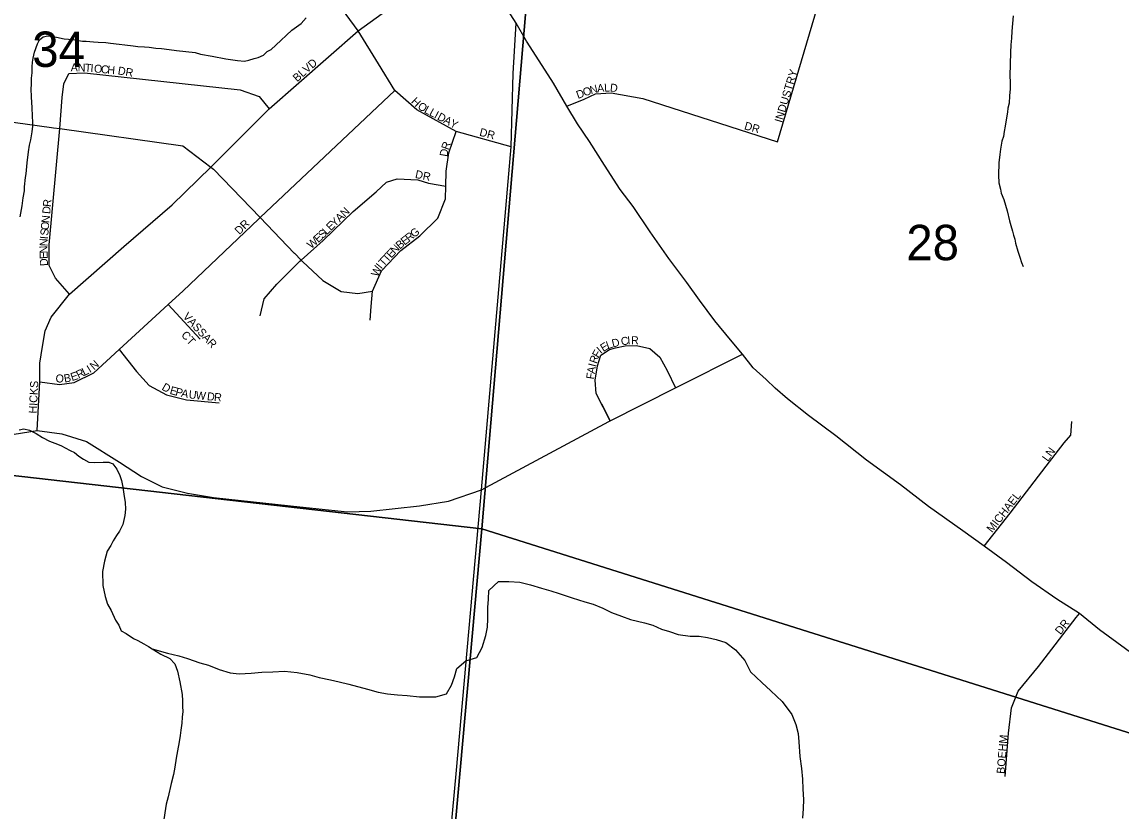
# Model space of a CAD drawing. Extents: x 1310247 to 1552180, y 377264 to 706493.
# Drawn here: x 1388764 to 1395630, y 491504 to 496435 of the extents above; entities that cross this region are included whole.
import ezdxf

# ---------------------------------------------------------------- set-up
doc = ezdxf.new("R2010")
doc.units = 0
for name, color, linetype in [('GM_X_City_Street', 7, 'Continuous'), ('GM_X_City_Street_Text', 7, 'Continuous'), ('GM_X_Minor_River', 7, 'Continuous'), ('GM_X_Section', 7, 'Continuous'), ('GM_X_Section_Text', 7, 'Continuous'), ('GM_X_State_Route', 7, 'Continuous')]:
    doc.layers.add(name, color=color, linetype=linetype)

msp = doc.modelspace()

# ---------------------------------------------------------------- linework, layer by layer
at = {"layer": 'GM_X_City_Street'}
for points in [[(1388858.2, 493882), (1388874.8, 494185.3), (1388875, 494301.6), (1388891.1, 494407.6), (1388908.9, 494503.6), (1388946.5, 494589.1), (1389061.3, 494733.4), (1389401.1, 495032), (1389702.7, 495292.1), (1389943.2, 495528.3), (1390307.7, 495891.8), (1390864.8, 496378.4), (1391178.7, 496608.5), (1391573.3, 496882.9), (1392264.6, 497329.3), (1392881.4, 497727.5), (1392929.2, 497820.9), (1392957.6, 498299.8)], [(1393484.5, 495686.5), (1393767, 496644.1), (1394171.8, 497915.6)], [(1391818.9, 495654.5), (1391475.3, 495749.8), (1391229.8, 495884.7), (1391093.9, 496007.1), (1390990.7, 496173.9), (1390864.8, 496378.4), (1390736.3, 496553.2), (1390644.8, 496707.3), (1390586.1, 496815.5), (1390559.3, 496872.4), (1390515, 496989.3), (1390484.1, 497166.6), (1390534, 497512.4), (1390552.9, 497662.5)], [(1391634.7, 493510.5), (1391818.9, 495654.5), (1391832.6, 496112.1), (1391851.9, 496427.8)], [(1389061.3, 494733.4), (1388973.1, 494833.3), (1388934.7, 494912.3), (1388933.2, 495042.4), (1388999.9, 495768.1), (1389014.6, 495963.4), (1389026.2, 496049.1), (1389057.5, 496113.5)], [(1389057.5, 496113.5), (1389153.6, 496117.7), (1390127.9, 496011.4), (1390245.1, 495969.2), (1390307.7, 495891.8)], [(1386085.1, 496049.9), (1386459, 496016.4), (1386828.5, 495981.4), (1387198.6, 495960.6), (1387320.9, 495952), (1388558.4, 495828.9), (1388571.9, 495827.6), (1388948.3, 495775.2), (1388960.6, 495773.5)], [(1388874.8, 494185.3), (1388998.5, 494169), (1389090.8, 494181.3), (1389212, 494241.2), (1389370.7, 494387.2), (1389677.2, 494669.2), (1389769.9, 494754.4), (1390240.6, 495203), (1390250.9, 495212.8), (1391093.9, 496007.1)], [(1392166.7, 495908), (1392275.4, 495951.6), (1392346.1, 495985.8), (1392444, 495992.2), (1392642.6, 495956.5), (1393484.5, 495686.5)], [(1388960.6, 495773.5), (1388999.9, 495768.1), (1389769.1, 495661), (1389943.2, 495528.3), (1389960.4, 495515.1), (1390250.9, 495212.8), (1390464.4, 494990.4), (1390465.7, 494989.2)], [(1390938.8, 494570.3), (1390944.4, 494656.5), (1390954.2, 494752.6), (1391010.6, 494879.9), (1391131.1, 495006.1), (1391248.9, 495098.1), (1391361, 495208.4), (1391409.3, 495329.8), (1391411.7, 495407.9), (1391414.6, 495502.3), (1391430.8, 495616.3), (1391475.3, 495749.8)], [(1390251.1, 494599.1), (1390277.1, 494704.9), (1390356.9, 494795.7), (1390499.6, 494939.5), (1390507.1, 494946.1), (1390646.1, 495069.2), (1390833.6, 495250.2), (1390976, 495374), (1391041.1, 495432.9), (1391107.6, 495453.8), (1391237.5, 495447.3), (1391303.2, 495428.1), (1391411.7, 495407.9)], [(1390465.7, 494989.2), (1390507.1, 494946.1), (1390515.6, 494937.2), (1390643.3, 494818.5), (1390758.1, 494750.2), (1390861.9, 494738.2), (1390954.2, 494752.6)], [(1389677.2, 494669.2), (1389876.2, 494451.6)], [(1392384.8, 494048.5), (1392438.3, 493942.4), (1392351.1, 494113.2), (1392345.2, 494195.7), (1392358.7, 494285.3), (1392379.6, 494351.8), (1392434.9, 494387.7), (1392472.5, 494397.8), (1392532.8, 494410.7), (1392602.9, 494413.4), (1392686, 494394.4), (1392748, 494339.9), (1392793.8, 494257.3), (1392846.2, 494148)], [(1388714.3, 493859.2), (1388858.2, 493882), (1389012.3, 493861.7), (1389167.7, 493813.7), (1389372.3, 493684.9), (1389511.2, 493594), (1389640, 493530.7), (1389798.3, 493489.2), (1389959.4, 493463.4), (1390442.1, 493410.8), (1390798.3, 493374.2), (1390942.3, 493378.5), (1391248, 493410.8), (1391428.6, 493439.9), (1391634.7, 493510.5), (1392430.8, 493938.6), (1392438.3, 493942.4), (1392846.2, 494148), (1392857.9, 494153.8), (1393264.8, 494359.7)], [(1389370.7, 494387.2), (1389480.2, 494250.3), (1389558.6, 494162.6), (1389667.5, 494104.4), (1389791, 494074.1), (1389994.7, 494054.3)], [(1394775.5, 493159.5), (1394937.4, 493366), (1395161.6, 493658.6), (1395274.5, 493805.7), (1395316.4, 493853.4), (1395322, 493937.6)], [(1391095.9, 487543.5), (1391100.6, 487596.7), (1391207.9, 488825.5), (1391477.6, 491759.9), (1391634.7, 493510.5)], [(1394905.7, 491718.9), (1394926.9, 491991.3), (1394945.9, 492149.4), (1394987.9, 492252.9), (1395114.8, 492407), (1395349.4, 492713.1), (1395369.6, 492737.7)]]:
    msp.add_lwpolyline(points, dxfattribs=at)
at = {"layer": 'GM_X_Minor_River'}
for points in [[(1389846.5, 496242.9), (1389878.4, 496234), (1389952.4, 496220.1), (1390038.3, 496203.8), (1390110.4, 496193.9), (1390154.5, 496190.8), (1390180.7, 496196.1), (1390215.2, 496207.3), (1390239.4, 496212.7), (1390272, 496228), (1390296.6, 496249.4), (1390321.1, 496262.8), (1390380.8, 496319.5), (1390415.9, 496352.8), (1390448.8, 496384.1), (1390508.2, 496424.8), (1390539.2, 496460.1)], [(1394956.6, 496472.9), (1394951.3, 496424.8), (1394948, 496376.7), (1394944.9, 496332.6), (1394941.8, 496292.5), (1394938.5, 496244.3), (1394934.6, 496097.8), (1394937.6, 496057.6), (1394936.5, 496017.4), (1394933.4, 495973.3), (1394930.1, 495927.2), (1394923.3, 495895.2), (1394920.6, 495871.2), (1394913.6, 495835.2), (1394906.2, 495783.2), (1394899.4, 495751.2), (1394894.5, 495719.2), (1394885.7, 495689.3), (1394881, 495665.3), (1394876.3, 495639.3), (1394871.5, 495607.3), (1394866.1, 495555.2), (1394864, 495476.9), (1394866.7, 495428.6), (1394875.8, 495390.2), (1394881.1, 495364), (1394898.2, 495325.4), (1394918.4, 495254.5), (1394932.8, 495191.9)], [(1388752.8, 495216.4), (1388764.7, 495286.4), (1388772, 495336.5), (1388779.2, 495380.5), (1388779.9, 495404.5), (1388785.4, 495462.7), (1388790.1, 495486.6), (1388795.9, 495554.8), (1388803.7, 495622.9), (1388810.9, 495664.9), (1388819.8, 495698.8), (1388827.1, 495748.8), (1388832, 495782.9), (1388832.7, 495807), (1388829.7, 495847.2), (1388827, 495897.5), (1388822.8, 495965.9), (1388822.1, 496016.1), (1388822.9, 496044.3), (1388823.9, 496084.4), (1388826.8, 496116.5), (1388827.8, 496154.6), (1388830.6, 496182.7), (1388833.2, 496208.7), (1388842.3, 496246.6), (1388861.7, 496298.4), (1388872.4, 496322.2), (1388897, 496341.7), (1388925.3, 496349), (1388949.4, 496346.3), (1388979.3, 496339.5), (1389027.3, 496330.3), (1389081.4, 496324.9), (1389141.4, 496315.3), (1389165.5, 496314.7), (1389211.6, 496311.5), (1389239.6, 496308.7), (1389287.8, 496305.5), (1389317.8, 496302.7), (1389371.9, 496295.3), (1389405.9, 496292.4), (1389458, 496285), (1389488, 496282.3), (1389530.1, 496279.2), (1389558.2, 496276.4), (1389600.2, 496271.3), (1389636.3, 496268.4), (1389682.4, 496263.2), (1389728.4, 496256), (1389786.5, 496250.5), (1389846.5, 496242.9)], [(1394932.8, 495191.9), (1394942.1, 495163.5), (1394951.2, 495127.1), (1394958.6, 495102.8), (1394965.9, 495076.5), (1394971.3, 495052.3), (1394984, 495001.8), (1394997.1, 494965.3), (1395008.2, 494930.8), (1395017.6, 494906.5)], [(1388745.8, 493886.8), (1388776.1, 493892), (1388810, 493883.1), (1388851.7, 493863.9), (1388891.2, 493838.8), (1388934.8, 493815.6), (1388986.5, 493796.2), (1389010.3, 493785.5), (1389034.1, 493772.9), (1389065.8, 493756), (1389091.5, 493743.3), (1389119.1, 493720.5), (1389148.7, 493703.6), (1389182.4, 493684.7), (1389218.5, 493681.8), (1389270.8, 493684.4), (1389306.9, 493683.5), (1389330.7, 493672.8), (1389356, 493640), (1389375, 493601.4), (1389386.2, 493569), (1389393.2, 493528.6), (1389400.1, 493484.2), (1389408.7, 493431.8), (1389409.6, 493389.6), (1389406.6, 493351.5), (1389393, 493293.6), (1389373.8, 493251.9), (1389355.1, 493226.2), (1389334.1, 493192.6), (1389319.3, 493162.9), (1389296.2, 493127.3), (1389278.5, 493065.5), (1389266.8, 493001.5), (1389268.5, 492913.1), (1389282.7, 492844.4), (1389297.5, 492795.8), (1389320.6, 492757.1), (1389347.1, 492696.1), (1389368.4, 492665.4), (1389383.6, 492630.9), (1389415.3, 492614), (1389460.6, 492582.7), (1389488.4, 492569.9), (1389526, 492548.9), (1389553.7, 492532.1), (1389577.4, 492517.4)], [(1389577.4, 492517.4), (1389673.5, 492491.3), (1389743.2, 492473.4), (1389797, 492457.9), (1389874.5, 492429.7), (1389928.3, 492416.1), (1389995.8, 492388.2), (1390065.4, 492368.2), (1390121.4, 492360.7), (1390195.8, 492364.7), (1390262.2, 492371), (1390330.5, 492373.1), (1390404.8, 492377.2), (1390482.9, 492369), (1390562.8, 492354.8), (1390620.5, 492339.2), (1390690.3, 492323.2), (1390746.2, 492311.7), (1390806, 492296), (1390921.5, 492264.8), (1390989.2, 492246.8), (1391047.2, 492237.2), (1391109.2, 492229.5), (1391169.3, 492225.9), (1391247.3, 492217.8), (1391299.4, 492216.4), (1391349.6, 492217), (1391416.4, 492235.3), (1391448, 492290.7), (1391465.5, 492342.5), (1391480.9, 492394.3), (1391536.4, 492443.1), (1391605.2, 492463.3), (1391639, 492524.7), (1391661.2, 492600.5), (1391672.6, 492652.4), (1391674.1, 492704.6), (1391674, 492775), (1391677.4, 492827.1), (1391680.9, 492881.3), (1391740.7, 492937.9), (1391804.9, 492938.2), (1391873, 492934.4), (1391940.8, 492916.5), (1392008.5, 492896.5), (1392068.2, 492880.8), (1392119.9, 492863.4), (1392201.5, 492837.1), (1392279, 492810.9), (1392332.8, 492797.3), (1392392.3, 492771.6), (1392445.7, 492744.1), (1392509.4, 492722.2), (1392565, 492700.7), (1392652.7, 492680.2), (1392704.4, 492664.7), (1392758, 492641.2), (1392809.7, 492625.7), (1392863.4, 492606.2), (1392937.4, 492596.2), (1392993.5, 492596.7), (1393045.5, 492589.2), (1393101.3, 492575.7), (1393161, 492556), (1393222, 492512.1), (1393280.3, 492444.2), (1393314.5, 492373), (1393384.9, 492306.8), (1393441.7, 492255), (1393512.1, 492188.8), (1393572.1, 492106.8), (1393598.4, 492043.8), (1393613, 491989.2), (1393617.6, 491936.8), (1393623.1, 491844.2), (1393633.1, 491769.6), (1393639.3, 491703.1), (1393641.6, 491640.8), (1393645.8, 491576.3), (1393644.3, 491520.1), (1393640.6, 491459.9)], [(1389577.4, 492517.4), (1389630.8, 492483.9), (1389688.3, 492456.3), (1389719.6, 492423.4), (1389734.5, 492378.8), (1389750.8, 492312.1), (1389764.7, 492231.4), (1389767.7, 492193.1), (1389766.8, 492157), (1389768, 492126.8), (1389765, 492090.7), (1389762, 492052.6), (1389756.8, 492008.6), (1389752, 491976.6), (1389744.9, 491936.6), (1389735.4, 491880.6), (1389728.1, 491834.5), (1389718.6, 491778.5), (1389711.4, 491732.5), (1389695.9, 491676.7), (1389677.6, 491592.8), (1389664.3, 491546.9), (1389659.6, 491518.9), (1389649.7, 491450.9)]]:
    msp.add_lwpolyline(points, dxfattribs=at)
at = {"layer": 'GM_X_Section'}
for points in [[(1386361.6, 499322.8), (1392089.7, 498619.6), (1391637.2, 493267.7), (1385887.9, 493921.2)], [(1392089.7, 498619.6), (1397269.5, 496943), (1396822, 491632.9), (1391637.2, 493267.7)], [(1385887.9, 493921.2), (1391637.2, 493267.7), (1391127.6, 487605), (1385461, 488464.6)], [(1391637.2, 493267.7), (1396822, 491632.9), (1396381.7, 486376.7), (1391127.6, 487605)]]:
    msp.add_lwpolyline(points, close=True, dxfattribs=at)
at = {"layer": 'GM_X_State_Route'}
msp.add_lwpolyline([(1395711.3, 492477.8), (1395494.4, 492636.7), (1395369.6, 492737.7), (1395228.5, 492826.8), (1395072.5, 492935.3), (1394913.6, 493057.1), (1394775.5, 493159.5), (1394641.8, 493254.6), (1394427.9, 493406.1), (1394251.1, 493541.3), (1394040.2, 493697.3), (1393847.1, 493848.8), (1393677.8, 493975), (1393547, 494079), (1393469.8, 494147.3), (1393411.8, 494200.8), (1393331.7, 494273.6), (1393264.8, 494359.7), (1393190.6, 494448.9), (1393092.5, 494567.7), (1392996, 494696.9), (1392917.2, 494806.9), (1392804.2, 494955.6), (1392688.2, 495122.5), (1392581.5, 495282.6), (1392500.4, 495388.1), (1392402.8, 495540.1), (1392309.5, 495687.5), (1392234.4, 495797.3), (1392166.7, 495908), (1392085.2, 496052.6), (1391975.4, 496220.1), (1391915.9, 496315.3), (1391851.9, 496427.8), (1391694.5, 496674)], dxfattribs=at)

# ---------------------------------------------------------------- texts
at = {"layer": 'GM_X_City_Street_Text'}
for s, rotation, p in [('BLVD', 41.75999, (1390482.9, 496057.1)), ('A', 359.90165, (1389068, 496125.5)), ('N', 358.92897, (1389111.8, 496125.4)), ('T', 355.5971, (1389155, 496124.7)), ('I', 354.7462, (1389189.9, 496122)), ('O', 354.6809, (1389211.8, 496120)), ('C', 354.6909, (1389255.6, 496115.9)), ('H', 354.69339, (1389295, 496112.2)), ('DR', 350.5367, (1389359.9, 496107.8)), ('INDUSTRY', 73.38024, (1393511.8, 495802)), ('N', 14.66179, (1392318.3, 495983.5)), ('A', 5.58228, (1392358.8, 495994.3)), ('L', 3.33517, (1392402.1, 495998.5)), ('D', 354.4286, (1392435.2, 496000.6)), ('D', 20.36033, (1392237, 495953.3)), ('O', 20.37301, (1392278.3, 495968.6)), ('H', 315.85003, (1391191.2, 495933.4)), ('O', 327.44216, (1391231.4, 495895.9)), ('L', 332.07961, (1391272.3, 495870)), ('L', 332.06652, (1391303.4, 495853.5)), ('I', 332.05796, (1391334.5, 495837.1)), ('D', 332.06015, (1391353.9, 495826.8)), ('A', 332.05672, (1391392.8, 495806.1)), ('Y', 332.05005, (1391431.7, 495785.5)), ('DR', 345.25814, (1391618, 495724.8)), ('DR', 344.47245, (1393272.5, 495764.4)), ('D', 79.99328, (1391421.2, 495590.2)), ('R', 70.39763, (1391428.3, 495631.4)), ('DR', 348.11596, (1391216.9, 495460.9)), ('R', 84.72312, (1388943.8, 495277.2)), ('N', 84.72182, (1388934.5, 495176.4)), ('D', 84.72182, (1388939.8, 495233.4)), ('Y', 44.29038, (1390718.3, 495151)), ('A', 44.29038, (1390749.8, 495181.7)), ('N', 44.29834, (1390781.3, 495212.5)), ('O', 84.72543, (1388930.5, 495132.6)), ('DR', 45, (1390121.8, 495102)), ('E', 44.29231, (1390693.1, 495126.4)), ('I', 84.87878, (1388925.3, 495075.7)), ('S', 84.73384, (1388927.2, 495097.5)), ('W', 41.24049, (1390571, 495014.4)), ('E', 41.75294, (1390614.4, 495052.4)), ('S', 43.72343, (1390642, 495077.1)), ('L', 44.26588, (1390667.8, 495101.8)), ('E', 38.29072, (1391154.1, 495036.7)), ('R', 38.27862, (1391181.7, 495058.5)), ('G', 39.1926, (1391213.5, 495083.5)), ('N', 91.42091, (1388924.1, 494989.2)), ('N', 86.94929, (1388923, 495032.2)), ('E', 46.94165, (1391070.5, 494955.3)), ('N', 45.85002, (1391094.3, 494980.9)), ('B', 39.85843, (1391124, 495011.5)), ('E', 91.83088, (1388925.2, 494954.2)), ('D', 91.83634, (1388926.6, 494910.2)), ('T', 47.435, (1391022.7, 494903.8)), ('T', 46.95163, (1391046.5, 494929.6)), ('W', 64.02522, (1390986.1, 494838.3)), ('I', 51.3197, (1391009.6, 494887.3)), ('VASSAR', 312.77005, (1389765.7, 494591.3)), ('CT', 312.71044, (1389755.3, 494475.7)), ('C', 8.58, (1392509.2, 494413)), ('I', 4.70375, (1392547.5, 494418.8)), ('R', 0.09713, (1392568.3, 494420.6)), ('I', 40.00147, (1392380, 494358.5)), ('E', 31.63614, (1392395.3, 494371.5)), ('L', 19.68782, (1392422.8, 494388.8)), ('D', 13.4664, (1392454.6, 494400.3)), ('R', 71.39992, (1392353.8, 494296.4)), ('F', 60.0179, (1392365.4, 494331.6)), ('R', 26.98272, (1389117.6, 494204.2)), ('L', 26.85827, (1389152.9, 494222.2)), ('I', 31.15726, (1389187.8, 494240.1)), ('N', 40.71551, (1389214, 494256.8)), ('A', 80.90237, (1392342, 494233.8)), ('I', 75.73584, (1392348.7, 494276.1)), ('HICKS', 87.27257, (1388856.2, 493987)), ('O', 355.06482, (1388971.9, 494184.3)), ('B', 10.09636, (1389030, 494181.2)), ('E', 18.30308, (1389076.5, 494190)), ('F', 81.31927, (1392336.7, 494199.1)), ('D', 329.74278, (1389632.7, 494139.1)), ('E', 344.73529, (1389683.9, 494111.5)), ('P', 346.17213, (1389719.1, 494101.8)), ('A', 348.13658, (1389755.1, 494093)), ('U', 353.88688, (1389803.6, 494083.1)), ('W', 354.50215, (1389847.9, 494078.4)), ('D', 354.50579, (1389918, 494071.6)), ('R', 354.49948, (1389961.8, 494067.4)), ('LN', 53.74584, (1395172, 493684.1)), ('MICHAEL', 52.04565, (1394824.6, 493239.9)), ('DR', 51.33663, (1395251.4, 492602)), ('BOEHM', 85.42633, (1394901.8, 491734.5))]:
    msp.add_text(s, height=50, rotation=rotation, dxfattribs=at).set_placement(p)
at = {"layer": 'GM_X_Section_Text'}
for s, p in [('34', (1388828.2, 496153.8)), ('28', (1394288.6, 494946))]:
    msp.add_text(s, height=221, rotation=0.00001, dxfattribs=at).set_placement(p)

doc.saveas('drawing.dxf')
